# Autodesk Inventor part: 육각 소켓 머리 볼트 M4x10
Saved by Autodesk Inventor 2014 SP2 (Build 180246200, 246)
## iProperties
Created: 2024-04
Part Number: 육각 소켓 머리 볼트 M4x10
Material: Generic
Document SubType Name: Modeling
Designer: Administrator
Density: 1 g/cm^3
Appearance: Default
Author: Administrator
Author: jhkim
Description: 6각머리 태핑 나사
Creation Date: 2024-04-08
Sending System: Autodesk Inventor 2025
Preprocessor: ST-DEVELOPER v20
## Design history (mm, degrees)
node "육각 소켓 머리 볼트 M4x101"
body "Solid1"
node "기준1"
